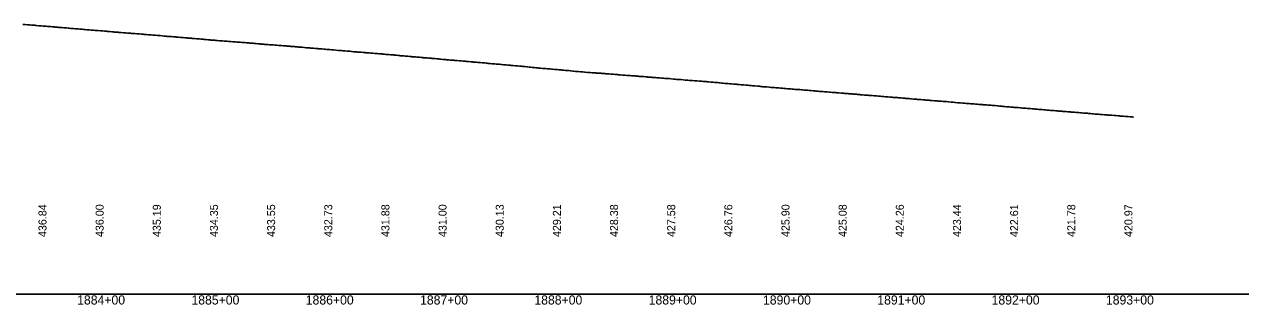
# Model space of a CAD drawing. Extents: x 2017200 to 2047700, y 854850 to 893350.
# Drawn here: x 2043330 to 2044394, y 856091 to 856336 of the extents above; entities that cross this region are included whole.
import ezdxf

# ---------------------------------------------------------------- set-up
doc = ezdxf.new("R2010")
doc.units = 0
for name, color, linetype in [('RD_DDB_Profile_EX', 7, 'Continuous'), ('RD_DDB_StaTX', 7, 'Continuous'), ('RD_DDB_StripGrade', 7, 'Continuous'), ('RD_GPK_Profile_Cell', 7, 'Continuous')]:
    doc.layers.add(name, color=color, linetype=linetype)

msp = doc.modelspace()

# ---------------------------------------------------------------- linework, layer by layer
at = {"layer": 'RD_DDB_Profile_EX'}
msp.add_lwpolyline([(2043328.3, 856336), (2043330.4, 856335.8), (2043332.4, 856335.7), (2043334.1, 856335.5), (2043334.4, 856335.5), (2043336, 856335.4), (2043336.5, 856335.3), (2043337.9, 856335.2), (2043338.7, 856335.2), (2043339.7, 856335.1), (2043340.4, 856335), (2043342.4, 856334.8), (2043344.1, 856334.7), (2043344.5, 856334.7), (2043346.1, 856334.5), (2043346.6, 856334.5), (2043348, 856334.4), (2043348.7, 856334.3), (2043349.8, 856334.2), (2043350.4, 856334.2), (2043352.4, 856334), (2043354.1, 856333.8), (2043354.5, 856333.8), (2043356.1, 856333.7), (2043356.6, 856333.6), (2043358.1, 856333.5), (2043358.8, 856333.5), (2043359.9, 856333.3), (2043360.5, 856333.3), (2043362.5, 856333.1), (2043364.2, 856333), (2043364.5, 856333), (2043366.2, 856332.8), (2043366.6, 856332.8), (2043368.1, 856332.7), (2043368.8, 856332.6), (2043370.1, 856332.5), (2043370.4, 856332.5), (2043372.5, 856332.3), (2043374.2, 856332.2), (2043374.5, 856332.1), (2043376.2, 856332), (2043376.6, 856332), (2043378.2, 856331.8), (2043378.9, 856331.8), (2043380.1, 856331.7), (2043381.4, 856331.6), (2043382.5, 856331.5), (2043384.2, 856331.3), (2043384.6, 856331.3), (2043386.2, 856331.1), (2043386.7, 856331.1), (2043388.2, 856331), (2043388.9, 856330.9), (2043390.2, 856330.8), (2043391.5, 856330.7), (2043392.3, 856330.6), (2043394.3, 856330.5), (2043396.3, 856330.3), (2043397.9, 856330.2), (2043398.3, 856330.2), (2043399.8, 856330), (2043400.3, 856330), (2043401.6, 856329.9), (2043402.3, 856329.8), (2043403.1, 856329.8), (2043404.3, 856329.7), (2043406.3, 856329.5), (2043407.9, 856329.4), (2043408.3, 856329.3), (2043409.9, 856329.2), (2043410.3, 856329.2), (2043411.7, 856329.1), (2043412.4, 856329), (2043413.3, 856328.9), (2043414.3, 856328.8), (2043416.3, 856328.7), (2043418, 856328.6), (2043418.4, 856328.5), (2043419.9, 856328.4), (2043420.4, 856328.4), (2043421.8, 856328.3), (2043422.5, 856328.2), (2043423.5, 856328.1), (2043424.3, 856328.1), (2043426.4, 856327.9), (2043428, 856327.8), (2043428.4, 856327.7), (2043430, 856327.6), (2043430.4, 856327.6), (2043431.9, 856327.5), (2043432.5, 856327.4), (2043433.6, 856327.3), (2043434.4, 856327.2), (2043436.4, 856327.1), (2043438.1, 856326.9), (2043438.4, 856326.9), (2043440, 856326.8), (2043440.5, 856326.7), (2043441.9, 856326.6), (2043442.6, 856326.6), (2043443.7, 856326.5), (2043444.4, 856326.4), (2043446.1, 856326.2), (2043446.4, 856326.2), (2043448.1, 856326.1), (2043448.5, 856326.1), (2043450.1, 856325.9), (2043450.6, 856325.9), (2043452, 856325.8), (2043452.7, 856325.7), (2043453.9, 856325.6), (2043454.4, 856325.5), (2043456.2, 856325.5), (2043456.5, 856325.4), (2043458.1, 856325.3), (2043458.5, 856325.3), (2043460.1, 856325.1), (2043460.6, 856325.1), (2043462.1, 856325), (2043462.7, 856324.9), (2043464, 856324.8), (2043464.5, 856324.8), (2043466.2, 856324.6), (2043466.5, 856324.6), (2043468.2, 856324.4), (2043468.6, 856324.4), (2043470.1, 856324.3), (2043470.7, 856324.2), (2043472.1, 856324.1), (2043472.8, 856324), (2043474, 856323.9), (2043475.2, 856323.8), (2043475.9, 856323.8), (2043476.5, 856323.7), (2043478.2, 856323.6), (2043478.6, 856323.5), (2043480.2, 856323.4), (2043480.7, 856323.4), (2043482.2, 856323.2), (2043482.8, 856323.2), (2043484.1, 856323.1), (2043485.2, 856323), (2043486, 856322.9), (2043486.8, 856322.8), (2043488.2, 856322.7), (2043488.6, 856322.7), (2043490.2, 856322.5), (2043490.7, 856322.5), (2043492.2, 856322.4), (2043492.9, 856322.3), (2043494.2, 856322.3), (2043495.3, 856322.2), (2043496.2, 856322.1), (2043497, 856322), (2043498.3, 856321.9), (2043498.7, 856321.9), (2043500.3, 856321.7), (2043500.8, 856321.7), (2043502.3, 856321.6), (2043503, 856321.5), (2043504.3, 856321.4), (2043505.4, 856321.3), (2043506.3, 856321.3), (2043507.2, 856321.2), (2043508.3, 856321.1), (2043509.9, 856321), (2043510.3, 856320.9), (2043511.9, 856320.8), (2043512.3, 856320.8), (2043513.8, 856320.7), (2043514.3, 856320.6), (2043515.6, 856320.5), (2043516.4, 856320.4), (2043517.3, 856320.4), (2043518.3, 856320.3), (2043520, 856320.1), (2043520.4, 856320.1), (2043521.9, 856320), (2043522.4, 856320), (2043523.8, 856319.8), (2043524.4, 856319.8), (2043525.7, 856319.7), (2043526.5, 856319.6), (2043527.5, 856319.6), (2043528.9, 856319.4), (2043530, 856319.4), (2043530.4, 856319.3), (2043532, 856319.2), (2043532.4, 856319.2), (2043533.9, 856319), (2043534.5, 856319), (2043535.8, 856318.9), (2043536.6, 856318.8), (2043537.6, 856318.7), (2043538.7, 856318.7), (2043539.1, 856318.6), (2043540.1, 856318.5), (2043540.4, 856318.5), (2043542, 856318.4), (2043542.5, 856318.3), (2043544, 856318.2), (2043544.5, 856318.2), (2043545.9, 856318.1), (2043546.6, 856318), (2043547.7, 856318), (2043548.8, 856317.9), (2043549.4, 856317.8), (2043550.1, 856317.7), (2043550.5, 856317.7), (2043552.1, 856317.6), (2043552.5, 856317.6), (2043554, 856317.4), (2043554.6, 856317.4), (2043556, 856317.3), (2043556.7, 856317.2), (2043557.8, 856317.1), (2043558.9, 856317.1), (2043559.6, 856317), (2043560.5, 856316.9), (2043562.1, 856316.8), (2043562.6, 856316.7), (2043564.1, 856316.6), (2043564.6, 856316.6), (2043566, 856316.5), (2043566.8, 856316.4), (2043567.9, 856316.3), (2043569, 856316.2), (2043569.7, 856316.1), (2043570.6, 856316.1), (2043572.1, 856315.9), (2043572.6, 856315.9), (2043574.1, 856315.8), (2043574.7, 856315.7), (2043576.1, 856315.6), (2043576.9, 856315.6), (2043578, 856315.5), (2043579.1, 856315.4), (2043579.9, 856315.3), (2043580.6, 856315.2), (2043582.2, 856315.1), (2043582.7, 856315.1), (2043584.2, 856314.9), (2043584.8, 856314.9), (2043586.1, 856314.8), (2043586.9, 856314.7), (2043588.1, 856314.6), (2043589.2, 856314.5), (2043590, 856314.5), (2043591.8, 856314.2), (2043592.7, 856314.2), (2043594.2, 856314.1), (2043594.8, 856314), (2043596.2, 856313.9), (2043597, 856313.9), (2043598.2, 856313.8), (2043599.3, 856313.7), (2043600.1, 856313.6), (2043602.2, 856313.4), (2043604.3, 856313.2), (2043604.9, 856313.2), (2043606.3, 856313.1), (2043607.1, 856313), (2043608.3, 856312.9), (2043609.3, 856312.8), (2043610.2, 856312.8), (2043611.9, 856312.6), (2043612.2, 856312.6), (2043612.5, 856312.5), (2043614.3, 856312.4), (2043615.8, 856312.3), (2043616.3, 856312.2), (2043617.7, 856312.1), (2043618.3, 856312.1), (2043619.5, 856312), (2043620.4, 856311.9), (2043621.3, 856311.8), (2043622.4, 856311.7), (2043622.8, 856311.7), (2043624.4, 856311.6), (2043625.9, 856311.4), (2043626.4, 856311.4), (2043627.8, 856311.3), (2043628.4, 856311.2), (2043629.6, 856311.1), (2043630.5, 856311.1), (2043631.4, 856311), (2043632.5, 856310.9), (2043633, 856310.8), (2043634.4, 856310.7), (2043635.9, 856310.6), (2043636.5, 856310.5), (2043637.8, 856310.4), (2043638.5, 856310.4), (2043639.7, 856310.3), (2043640.6, 856310.2), (2043641.5, 856310.1), (2043642.7, 856310.1), (2043643.2, 856310), (2043644.2, 856309.9), (2043644.8, 856309.9), (2043645.9, 856309.7), (2043646.5, 856309.7), (2043647.9, 856309.6), (2043648.6, 856309.5), (2043649.8, 856309.4), (2043650.6, 856309.3), (2043651.6, 856309.3), (2043652.8, 856309.2), (2043653.4, 856309.1), (2043655.1, 856309), (2043656.6, 856308.8), (2043657.9, 856308.7), (2043658.7, 856308.6), (2043659.9, 856308.5), (2043660.7, 856308.5), (2043661.7, 856308.4), (2043662.9, 856308.3), (2043663.6, 856308.2), (2043665.2, 856308.1), (2043666.7, 856307.9), (2043668, 856307.8), (2043668.7, 856307.7), (2043669.9, 856307.6), (2043670.8, 856307.6), (2043671.9, 856307.5), (2043673, 856307.4), (2043673.7, 856307.3), (2043675.4, 856307.2), (2043676.7, 856307), (2043678.1, 856306.9), (2043678.8, 856306.8), (2043680, 856306.7), (2043680.9, 856306.7), (2043682, 856306.6), (2043683.1, 856306.5), (2043683.8, 856306.4), (2043685.6, 856306.3), (2043686.1, 856306.2), (2043687.6, 856306.1), (2043688.1, 856306), (2043688.9, 856306), (2043690.1, 856305.9), (2043691, 856305.8), (2043692.1, 856305.7), (2043693.2, 856305.6), (2043694, 856305.5), (2043695.8, 856305.4), (2043696.5, 856305.3), (2043697.8, 856305.2), (2043698.1, 856305.2), (2043699, 856305.1), (2043700.2, 856305), (2043701.1, 856304.9), (2043702.1, 856304.8), (2043703.3, 856304.7), (2043704.1, 856304.7), (2043705.7, 856304.6), (2043706, 856304.5), (2043707, 856304.4), (2043708.2, 856304.3), (2043710.3, 856304.1), (2043711.2, 856304), (2043712.2, 856304), (2043713.4, 856303.9), (2043714.2, 856303.8), (2043715.8, 856303.7), (2043716.2, 856303.6), (2043717.5, 856303.5), (2043718.3, 856303.4), (2043720.3, 856303.2), (2043721.6, 856303.1), (2043722.3, 856303), (2043723.4, 856303), (2043724.3, 856302.9), (2043725.2, 856302.8), (2043726.3, 856302.7), (2043726.8, 856302.7), (2043728, 856302.6), (2043728.4, 856302.6), (2043730, 856302.4), (2043730.4, 856302.3), (2043731, 856302.3), (2043732.4, 856302.2), (2043733.5, 856302.1), (2043734.5, 856302), (2043735.3, 856301.9), (2043736.5, 856301.8), (2043737, 856301.8), (2043738.5, 856301.6), (2043740.2, 856301.5), (2043740.6, 856301.5), (2043741.1, 856301.4), (2043742.5, 856301.3), (2043743.6, 856301.2), (2043744.6, 856301.2), (2043745.4, 856301.1), (2043746.6, 856301), (2043747.2, 856300.9), (2043748.9, 856300.7), (2043750.5, 856300.6), (2043750.8, 856300.6), (2043751.2, 856300.5), (2043752.6, 856300.4), (2043753.7, 856300.3), (2043754.7, 856300.2), (2043755.6, 856300.1), (2043756.8, 856300), (2043757.4, 856300), (2043759, 856299.8), (2043759.4, 856299.8), (2043761, 856299.7), (2043761.3, 856299.6), (2043762.7, 856299.5), (2043763.8, 856299.4), (2043764.8, 856299.3), (2043765.7, 856299.2), (2043766.9, 856299.1), (2043767.5, 856299), (2043769.3, 856298.8), (2043769.8, 856298.8), (2043771.2, 856298.6), (2043771.5, 856298.6), (2043772.8, 856298.5), (2043773.9, 856298.4), (2043774.8, 856298.3), (2043775.8, 856298.2), (2043777, 856298), (2043777.7, 856298), (2043779.2, 856297.9), (2043779.5, 856297.8), (2043780.3, 856297.7), (2043781.6, 856297.6), (2043782.8, 856297.5), (2043784, 856297.4), (2043784.9, 856297.4), (2043785.9, 856297.3), (2043787.1, 856297.2), (2043787.8, 856297.1), (2043789.3, 856297), (2043789.7, 856297), (2043790.8, 856296.9), (2043791.7, 856296.8), (2043793.6, 856296.5), (2043794.1, 856296.5), (2043795, 856296.5), (2043796, 856296.4), (2043797.2, 856296.3), (2043798, 856296.2), (2043799.4, 856296.1), (2043799.8, 856296), (2043801.2, 856295.9), (2043801.7, 856295.9), (2043803.3, 856295.6), (2043803.8, 856295.6), (2043804.4, 856295.6), (2043805.1, 856295.6), (2043806.1, 856295.5), (2043807.3, 856295.4), (2043808.1, 856295.3), (2043809.5, 856295.1), (2043810, 856295), (2043811.9, 856294.9), (2043813.6, 856294.8), (2043813.9, 856294.8), (2043814.5, 856294.7), (2043816.2, 856294.5), (2043817.4, 856294.4), (2043818.2, 856294.4), (2043819.6, 856294.3), (2043820.2, 856294.2), (2043822.2, 856294), (2043824.1, 856293.9), (2043824.6, 856293.8), (2043826.3, 856293.7), (2043827.4, 856293.6), (2043828.3, 856293.5), (2043829.7, 856293.5), (2043830.3, 856293.4), (2043832.3, 856293.3), (2043832.7, 856293.2), (2043834.3, 856293.2), (2043834.7, 856293.1), (2043836.4, 856293), (2043837.5, 856292.9), (2043838.4, 856292.8), (2043839.3, 856292.7), (2043840.4, 856292.6), (2043841.1, 856292.6), (2043842.7, 856292.5), (2043843.1, 856292.4), (2043844.5, 856292.3), (2043844.9, 856292.3), (2043846.5, 856292.1), (2043847.6, 856292.1), (2043848.5, 856292), (2043849.5, 856291.9), (2043850.6, 856291.9), (2043851.2, 856291.8), (2043852.9, 856291.7), (2043853.6, 856291.6), (2043855, 856291.6), (2043856.6, 856291.4), (2043857.7, 856291.3), (2043858.6, 856291.2), (2043859.6, 856291.2), (2043860.7, 856291.1), (2043861.4, 856291), (2043862.8, 856291), (2043863.1, 856290.9), (2043864.1, 856290.9), (2043864.9, 856290.8), (2043866.5, 856290.6), (2043866.9, 856290.6), (2043867.8, 856290.5), (2043868.7, 856290.5), (2043869.7, 856290.4), (2043870.8, 856290.3), (2043871.6, 856290.3), (2043872.9, 856290.1), (2043873.3, 856290.1), (2043874.5, 856290), (2043875.2, 856289.9), (2043877.1, 856289.8), (2043877.9, 856289.7), (2043878.8, 856289.6), (2043879.8, 856289.5), (2043880.9, 856289.5), (2043881.7, 856289.4), (2043883, 856289.3), (2043883.5, 856289.3), (2043885.3, 856289.1), (2043886.9, 856289), (2043887.3, 856289), (2043887.9, 856288.9), (2043888.9, 856288.8), (2043889.9, 856288.7), (2043891, 856288.7), (2043891.8, 856288.6), (2043893.2, 856288.5), (2043893.7, 856288.5), (2043895.5, 856288.3), (2043897.5, 856288.1), (2043898, 856288.1), (2043899, 856288), (2043900, 856287.9), (2043901.1, 856287.9), (2043902, 856287.8), (2043903.3, 856287.7), (2043903.9, 856287.7), (2043905.9, 856287.5), (2043907.7, 856287.3), (2043908.1, 856287.3), (2043909, 856287.2), (2043910.1, 856287.1), (2043911.2, 856287), (2043912.1, 856287), (2043913.4, 856286.9), (2043914, 856286.8), (2043915.9, 856286.7), (2043916.4, 856286.7), (2043917.9, 856286.5), (2043918.2, 856286.5), (2043920.2, 856286.3), (2043921.2, 856286.2), (2043922.2, 856286.2), (2043923.5, 856286.1), (2043924.1, 856286), (2043926.1, 856285.9), (2043926.9, 856285.8), (2043928.4, 856285.7), (2043930.3, 856285.5), (2043931.3, 856285.4), (2043932.3, 856285.3), (2043933.6, 856285.2), (2043934.3, 856285.2), (2043935.9, 856285), (2043936.3, 856285), (2043937.4, 856284.9), (2043938.3, 856284.9), (2043939.8, 856284.6), (2043940.3, 856284.6), (2043941, 856284.6), (2043942.4, 856284.4), (2043943.4, 856284.4), (2043944.4, 856284.3), (2043945.2, 856284.2), (2043946.4, 856284.1), (2043946.8, 856284.1), (2043947.8, 856284), (2043948.4, 856283.9), (2043950.1, 856283.8), (2043950.5, 856283.7), (2043951.1, 856283.7), (2043952.5, 856283.6), (2043953.5, 856283.5), (2043954.5, 856283.4), (2043955.3, 856283.3), (2043956.6, 856283.2), (2043957, 856283.2), (2043958.3, 856283.1), (2043958.7, 856283), (2043960.7, 856282.9), (2043961.3, 856282.8), (2043962.6, 856282.7), (2043963.6, 856282.6), (2043964.6, 856282.5), (2043965.5, 856282.4), (2043966.7, 856282.3), (2043967.2, 856282.3), (2043968.8, 856282.1), (2043970.9, 856282), (2043971.4, 856281.9), (2043972.7, 856281.8), (2043973.7, 856281.7), (2043974.7, 856281.6), (2043975.6, 856281.5), (2043976.8, 856281.4), (2043977.4, 856281.4), (2043979.2, 856281.3), (2043981.1, 856281.1), (2043981.5, 856281.1), (2043982.7, 856280.9), (2043983.8, 856280.8), (2043984.8, 856280.7), (2043985.7, 856280.7), (2043986.9, 856280.6), (2043987.6, 856280.5), (2043989.3, 856280.4), (2043989.7, 856280.4), (2043991.2, 856280.2), (2043991.6, 856280.2), (2043992.8, 856280.1), (2043993.9, 856280), (2043994.9, 856279.9), (2043995.9, 856279.8), (2043997, 856279.7), (2043997.7, 856279.7), (2043999.5, 856279.6), (2044000.2, 856279.5), (2044001.4, 856279.4), (2044001.7, 856279.4), (2044002.9, 856279.3), (2044004, 856279.1), (2044005, 856279.1), (2044006, 856279), (2044007.1, 856278.9), (2044007.9, 856278.9), (2044009.4, 856278.7), (2044009.7, 856278.7), (2044010.6, 856278.6), (2044011.9, 856278.5), (2044012.9, 856278.4), (2044014.1, 856278.3), (2044015.1, 856278.3), (2044016.1, 856278.2), (2044017.2, 856278.1), (2044018, 856278.1), (2044019.5, 856277.9), (2044019.9, 856277.9), (2044021.1, 856277.8), (2044022, 856277.7), (2044024.2, 856277.5), (2044025.1, 856277.4), (2044026.2, 856277.3), (2044027.3, 856277.3), (2044028.1, 856277.2), (2044029.6, 856277.1), (2044030.1, 856277), (2044031.6, 856276.9), (2044032, 856276.9), (2044033.6, 856276.7), (2044034, 856276.7), (2044034.6, 856276.6), (2044036.3, 856276.5), (2044037.4, 856276.4), (2044038.3, 856276.3), (2044039.7, 856276.3), (2044040.2, 856276.2), (2044042.2, 856276.1), (2044044.2, 856275.9), (2044044.8, 856275.8), (2044046.4, 856275.7), (2044047.5, 856275.6), (2044048.4, 856275.5), (2044049.3, 856275.5), (2044050.4, 856275.4), (2044051, 856275.3), (2044052.5, 856275.3), (2044054.1, 856275.1), (2044054.4, 856275), (2044054.9, 856275), (2044056.4, 856274.9), (2044057.6, 856274.8), (2044058.5, 856274.7), (2044059.4, 856274.7), (2044060.5, 856274.6), (2044061.2, 856274.5), (2044063, 856274.4), (2044064.6, 856274.2), (2044065, 856274.2), (2044066.5, 856274.1), (2044067.7, 856274), (2044068.6, 856273.9), (2044069.5, 856273.8), (2044070.6, 856273.7), (2044071.3, 856273.7), (2044073, 856273.5), (2044073.5, 856273.5), (2044074.8, 856273.4), (2044075.1, 856273.4), (2044076.6, 856273.2), (2044077.8, 856273.1), (2044078.7, 856273.1), (2044079.7, 856273), (2044080.7, 856272.9), (2044081.5, 856272.8), (2044082.9, 856272.7), (2044083.2, 856272.7), (2044083.9, 856272.6), (2044085.2, 856272.5), (2044086.7, 856272.4), (2044087.9, 856272.3), (2044088.7, 856272.2), (2044089.8, 856272.1), (2044090.8, 856272.1), (2044091.6, 856272), (2044093, 856271.9), (2044093.4, 856271.9), (2044094.4, 856271.8), (2044095.4, 856271.7), (2044096.7, 856271.6), (2044097.9, 856271.5), (2044098.8, 856271.4), (2044099.9, 856271.3), (2044100.9, 856271.2), (2044101.8, 856271.2), (2044103.1, 856271.1), (2044103.6, 856271.1), (2044104.9, 856271), (2044105.5, 856270.9), (2044107.4, 856270.7), (2044108, 856270.6), (2044108.9, 856270.6), (2044110, 856270.5), (2044111, 856270.4), (2044111.9, 856270.4), (2044113.2, 856270.2), (2044113.8, 856270.2), (2044115.6, 856270.1), (2044117.6, 856269.9), (2044118.1, 856269.8), (2044119, 856269.7), (2044120.1, 856269.7), (2044121.1, 856269.6), (2044122, 856269.5), (2044123.3, 856269.4), (2044123.9, 856269.4), (2044125.8, 856269.2), (2044127.5, 856269.1), (2044127.8, 856269), (2044128.3, 856269), (2044129.1, 856268.9), (2044130.2, 856268.8), (2044131.2, 856268.8), (2044132.1, 856268.7), (2044133.4, 856268.6), (2044134.1, 856268.5), (2044136, 856268.4), (2044136.3, 856268.4), (2044138, 856268.2), (2044138.4, 856268.2), (2044140.3, 856268), (2044141.3, 856267.9), (2044142.2, 856267.9), (2044143.5, 856267.8), (2044144.2, 856267.7), (2044146.2, 856267.5), (2044146.8, 856267.5), (2044148.2, 856267.4), (2044148.5, 856267.3), (2044150.3, 856267.2), (2044151.4, 856267.1), (2044152.3, 856267), (2044153.6, 856266.9), (2044154.3, 856266.9), (2044156.3, 856266.7), (2044157.2, 856266.6), (2044158.6, 856266.5), (2044160.4, 856266.4), (2044161.6, 856266.3), (2044162.4, 856266.2), (2044163.4, 856266.1), (2044164.5, 856266), (2044165.2, 856266), (2044166.5, 856265.9), (2044166.8, 856265.9), (2044167.7, 856265.8), (2044168.5, 856265.7), (2044170.1, 856265.6), (2044170.6, 856265.6), (2044171.3, 856265.5), (2044172.5, 856265.4), (2044173.5, 856265.3), (2044174.6, 856265.2), (2044175.3, 856265.2), (2044176.6, 856265.1), (2044177.1, 856265), (2044178.2, 856264.9), (2044178.9, 856264.9), (2044180.8, 856264.7), (2044181.4, 856264.6), (2044182.6, 856264.5), (2044183.6, 856264.4), (2044184.7, 856264.4), (2044185.5, 856264.3), (2044186.8, 856264.2), (2044187.3, 856264.1), (2044188.9, 856264), (2044190.6, 856263.9), (2044191, 856263.8), (2044191.5, 856263.8), (2044192.7, 856263.7), (2044193.8, 856263.6), (2044194.8, 856263.5), (2044195.6, 856263.4), (2044196.9, 856263.3), (2044197.4, 856263.2), (2044199.1, 856263.2), (2044200.8, 856263), (2044201.1, 856262.9), (2044201.6, 856262.9), (2044202.8, 856262.8), (2044203.9, 856262.7), (2044204.9, 856262.6), (2044205.8, 856262.6), (2044207, 856262.5), (2044207.6, 856262.4), (2044209.6, 856262.3), (2044211.3, 856262.1), (2044211.8, 856262.1), (2044212.9, 856262), (2044214, 856261.9), (2044215, 856261.8), (2044215.9, 856261.8), (2044217.2, 856261.6), (2044217.8, 856261.6), (2044219.6, 856261.5), (2044220.1, 856261.4), (2044221.5, 856261.3), (2044221.9, 856261.3), (2044223, 856261.1), (2044224.1, 856261), (2044225.1, 856261), (2044226, 856260.9), (2044227.3, 856260.8), (2044227.9, 856260.8), (2044229.8, 856260.6), (2044230.5, 856260.6), (2044232, 856260.4), (2044233.8, 856260.3), (2044234.5, 856260.2), (2044235.2, 856260.1), (2044236.1, 856260.1), (2044237.4, 856260), (2044238, 856259.9), (2044239.7, 856259.8), (2044240, 856259.8), (2044241, 856259.7), (2044242.1, 856259.6), (2044243.9, 856259.4), (2044244.7, 856259.4), (2044245.3, 856259.3), (2044246.2, 856259.2), (2044247.5, 856259.1), (2044248.2, 856259.1), (2044249.8, 856258.9), (2044250.1, 856258.9), (2044251.5, 856258.8), (2044252.1, 856258.8), (2044253.7, 856258.6), (2044254.1, 856258.6), (2044254.8, 856258.6), (2044256.3, 856258.4), (2044257.6, 856258.3), (2044258.3, 856258.3), (2044259.9, 856258.2), (2044260.3, 856258.1), (2044261.9, 856258), (2044262.3, 856258), (2044263.9, 856257.8), (2044264.3, 856257.8), (2044264.9, 856257.8), (2044266.4, 856257.6), (2044267.4, 856257.5), (2044268.4, 856257.5), (2044269.2, 856257.4), (2044270.4, 856257.3), (2044270.9, 856257.3), (2044272.5, 856257.1), (2044274.2, 856257), (2044274.5, 856257), (2044275, 856257), (2044276.5, 856256.8), (2044277.5, 856256.7), (2044278.6, 856256.7), (2044279.3, 856256.6), (2044280.6, 856256.5), (2044281.1, 856256.5), (2044282.9, 856256.3), (2044284.7, 856256.2), (2044286.1, 856256.1), (2044286.7, 856256), (2044287.7, 856255.9), (2044288.7, 856255.8), (2044289.5, 856255.8), (2044290.7, 856255.7), (2044291.3, 856255.6), (2044293, 856255.5), (2044293.3, 856255.5), (2044294.9, 856255.3), (2044295.3, 856255.3), (2044296.9, 856255.1), (2044297.8, 856255.1), (2044298.8, 856255), (2044299.6, 856254.9), (2044300, 856254.9)], dxfattribs=at)
at = {"layer": 'RD_GPK_Profile_Cell'}
msp.add_line((2020500, 856100), (2047700, 856100), dxfattribs=at)

# ---------------------------------------------------------------- texts
at = {"layer": 'RD_DDB_StaTX'}
for s, p in [('1884+00', (2043375.8, 856091)), ('1885+00', (2043475.8, 856091)), ('1886+00', (2043575.8, 856091)), ('1887+00', (2043675.8, 856091)), ('1888+00', (2043775.8, 856091)), ('1889+00', (2043875.8, 856091)), ('1890+00', (2043975.8, 856091)), ('1891+00', (2044075.8, 856091)), ('1892+00', (2044175.8, 856091)), ('1893+00', (2044275.8, 856091))]:
    msp.add_text(s, height=8, dxfattribs=at).set_placement(p)
at = {"layer": 'RD_DDB_StripGrade'}
for s, p in [('436.84', (2043349, 856150)), ('436.00', (2043399, 856150)), ('435.19', (2043449, 856150)), ('434.35', (2043499, 856150)), ('433.55', (2043549, 856150)), ('432.73', (2043599, 856150)), ('431.88', (2043649, 856150)), ('431.00', (2043699, 856150)), ('430.13', (2043749, 856150)), ('429.21', (2043799, 856150)), ('428.38', (2043849, 856150)), ('427.58', (2043899, 856150)), ('426.76', (2043949, 856150)), ('425.90', (2043999, 856150)), ('425.08', (2044049, 856150)), ('424.26', (2044099, 856150)), ('423.44', (2044149, 856150)), ('422.61', (2044199, 856150)), ('421.78', (2044249, 856150)), ('420.97', (2044299, 856150))]:
    msp.add_text(s, height=7, rotation=90, dxfattribs=at).set_placement(p)

doc.saveas('drawing.dxf')
